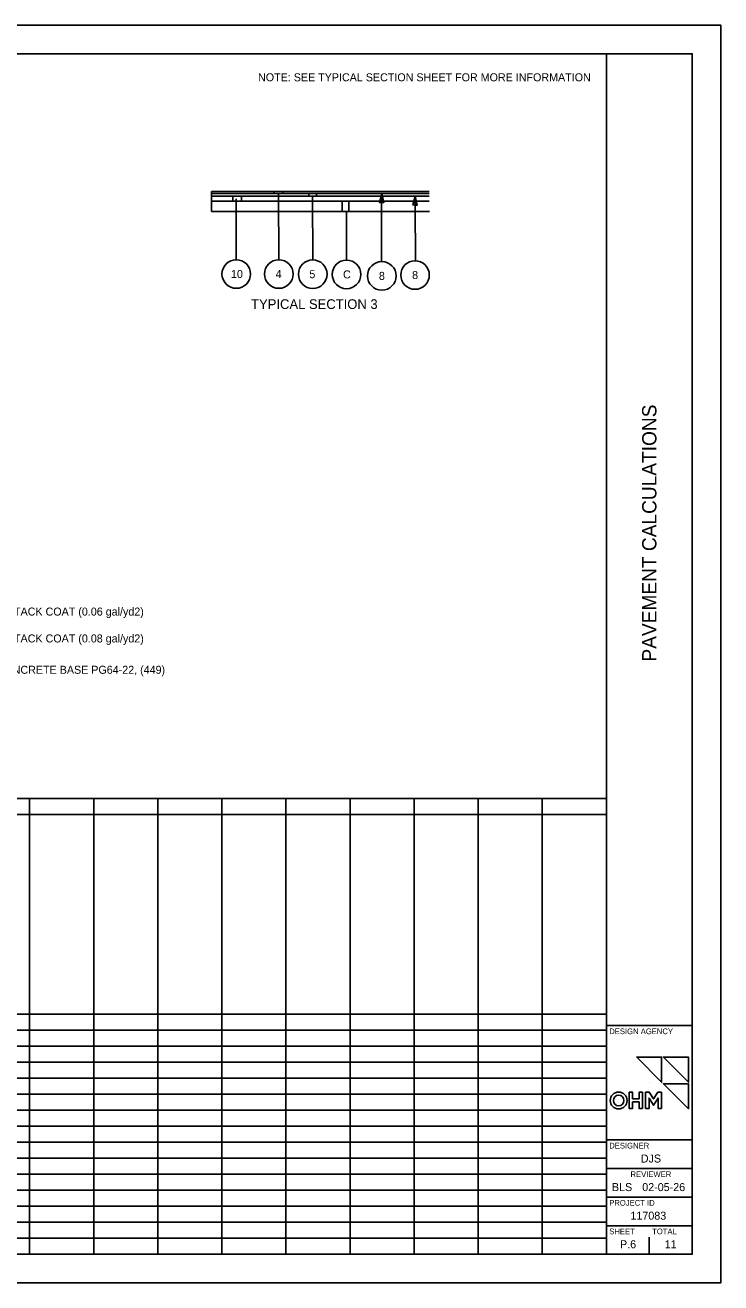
# Model space of a CAD drawing. Extents: x 0 to 34, y 0 to 22.
# Drawn here: x 21.84 to 34, y 0 to 22 of the extents above; entities that cross this region are included whole.
import ezdxf

# ---------------------------------------------------------------- set-up
doc = ezdxf.new("R2010")
doc.units = 0
for name, color, linetype in [('Default', 7, 'Continuous'), ('PV_P_EOP', 7, 'Continuous'), ('SC_Shading2', 7, 'Continuous'), ('SH_Border', 7, 'Continuous'), ('SH_Cut_Line', 7, 'Continuous'), ('SH_Data', 7, 'Continuous'), ('SH_Text', 7, 'Continuous'), ('TX_P_Misc', 7, 'Continuous')]:
    doc.layers.add(name, color=color, linetype=linetype)

msp = doc.modelspace()

# ---------------------------------------------------------------- linework, layer by layer
at = {"layer": 'Default'}
for p, q in [((25.101, 19.055), (28.904, 19.055)), ((25.101, 19.01), (28.905, 19.01)), ((25.101, 18.921), (28.905, 18.921)), ((25.101, 18.742), (28.91, 18.742)), ((1.5, 8.472), (32, 8.472)), ((21.921, 8.472), (21.921, 0.502)), ((23.041, 8.472), (23.041, 0.502)), ((24.161, 8.472), (24.161, 0.502)), ((25.281, 8.472), (25.281, 0.502)), ((26.401, 8.472), (26.401, 0.502)), ((27.521, 8.472), (27.521, 0.502)), ((28.64, 8.472), (28.64, 0.502)), ((29.76, 8.472), (29.76, 0.502)), ((30.88, 8.472), (30.88, 0.502)), ((32, 8.472), (32, 0.502)), ((11.842, 8.192), (32, 8.192)), ((7.363, 4.701), (32, 4.701)), ((1.5, 4.421), (32, 4.421)), ((1.5, 4.141), (32, 4.141)), ((1.5, 3.861), (32, 3.861)), ((1.5, 3.581), (32, 3.581)), ((1.5, 3.301), (32, 3.301)), ((1.5, 3.021), (32, 3.021)), ((1.5, 2.741), (32, 2.741)), ((1.5, 2.461), (32, 2.461)), ((1.5, 2.181), (32, 2.181)), ((1.5, 1.901), (32, 1.901)), ((1.5, 1.621), (32, 1.621)), ((1.5, 1.341), (32, 1.341)), ((1.5, 1.061), (32, 1.061)), ((1.5, 0.782), (32, 0.782)), ((1.5, 0.502), (32, 0.502))]:
    msp.add_line(p, q, dxfattribs=at)
for points in [[(32.966, 3.948), (32.966, 3.51), (32.53, 3.948)], [(33.433, 3.948), (33.433, 3.51), (32.997, 3.948)], [(32.397, 3.333), (32.457, 3.333), (32.457, 3.22), (32.571, 3.22), (32.571, 3.333), (32.631, 3.333), (32.631, 3.052), (32.571, 3.052), (32.571, 3.166), (32.457, 3.166), (32.457, 3.052), (32.397, 3.052)], [(32.9, 3.335), (32.963, 3.335), (32.963, 3.052), (32.903, 3.052), (32.903, 3.233), (32.824, 3.108), (32.745, 3.233), (32.745, 3.052), (32.685, 3.052), (32.685, 3.335), (32.748, 3.335), (32.824, 3.216)], [(33.433, 3.483), (33.433, 3.045), (32.997, 3.483)]]:
    msp.add_lwpolyline(points, close=True, dxfattribs=at)
at = {"layer": 'PV_P_EOP'}
for q in [(28.903, 19.088), (25.101, 18.742)]:
    msp.add_line((25.101, 19.088), q, dxfattribs=at)
at = {"layer": 'SC_Shading2'}
msp.add_lwpolyline([(27.501, 18.921), (27.383, 18.921), (27.383, 18.742), (27.501, 18.742)], close=True, dxfattribs=at)
at = {"layer": 'SH_Border'}
for p, q in [((32, 0.5), (32, 21.5)), ((32, 4.5), (33.5, 4.5)), ((32, 2.5), (33.5, 2.5)), ((32, 2), (33.5, 2)), ((32, 1.5), (33.5, 1.5)), ((32, 1), (33.5, 1))]:
    msp.add_line(p, q, dxfattribs=at)
msp.add_lwpolyline([(1.5, 21.5), (33.5, 21.5), (33.5, 0.5), (1.5, 0.5)], close=True, dxfattribs=at)
at = {"layer": 'SH_Cut_Line'}
msp.add_lwpolyline([(0, 0), (34, 0), (34, 22), (0, 22)], close=True, dxfattribs=at)
at = {"layer": 'SH_Data'}
for p, q in [((32.75, 3.5), (32.75, 3.5)), ((32.375, 0.675), (32.375, 0.675)), ((32.75, 0.5), (32.75, 0.8))]:
    msp.add_line(p, q, dxfattribs=at)
at = {"layer": 'SH_Text'}
for p, q in [((25.533, 17.897), (25.529, 18.962)), ((26.276, 17.897), (26.271, 19.055)), ((26.868, 17.894), (26.863, 19.01)), ((27.459, 17.89), (27.456, 18.742)), ((28.07, 17.864), (28.073, 18.899)), ((28.663, 17.879), (28.657, 18.854))]:
    msp.add_line(p, q, dxfattribs=at)
for points in [[(25.623, 19.008), (25.624, 18.921), (25.472, 18.921), (25.472, 19.008)], [(26.346, 19.088), (26.347, 19.055), (26.195, 19.055), (26.194, 19.088)], [(26.934, 19.055), (26.935, 19.01), (26.798, 19.01), (26.798, 19.055)], [(28.073, 18.899), (28.075, 19.055), (28.034, 18.9)], [(28.073, 18.899), (28.075, 19.055), (28.112, 18.899)], [(28.657, 18.854), (28.659, 19.01), (28.618, 18.855)], [(28.657, 18.854), (28.659, 19.01), (28.696, 18.854)]]:
    msp.add_lwpolyline(points, close=True, dxfattribs=at)
for centre in [(25.533, 17.647), (26.276, 17.647), (26.868, 17.644), (27.459, 17.64), (28.076, 17.614), (28.656, 17.629)]:
    msp.add_circle(centre, 0.25, dxfattribs=at)
at = {"layer": 'TX_P_Misc'}
for p, q in [((32.745, 3.052), (32.745, 3.233)), ((32.745, 3.233), (32.824, 3.108)), ((32.824, 3.108), (32.903, 3.233)), ((32.903, 3.233), (32.903, 3.052))]:
    msp.add_line(p, q, dxfattribs=at)
for points in [[(32.53, 3.948), (32.966, 3.51), (32.966, 3.948), (32.53, 3.948)], [(32.997, 3.948), (33.433, 3.51), (33.433, 3.948), (32.997, 3.948)], [(32.824, 3.216), (32.748, 3.335), (32.685, 3.335), (32.685, 3.052), (32.745, 3.052)], [(32.903, 3.052), (32.963, 3.052), (32.963, 3.335), (32.9, 3.335), (32.824, 3.216)], [(32.997, 3.483), (33.433, 3.045), (33.433, 3.483), (32.997, 3.483)]]:
    msp.add_lwpolyline(points, dxfattribs=at)
msp.add_lwpolyline([(32.397, 3.333), (32.457, 3.333), (32.457, 3.22), (32.571, 3.22), (32.571, 3.333), (32.631, 3.333), (32.631, 3.052), (32.571, 3.052), (32.571, 3.166), (32.457, 3.166), (32.457, 3.052), (32.397, 3.052)], close=True, dxfattribs=at)
for radius in [0.148, 0.148, 0.0927, 0.0927]:
    msp.add_circle((32.215, 3.19), radius, dxfattribs=at)

# ---------------------------------------------------------------- texts
at = {"layer": 'Default'}
for s, p in [('NOTE: SEE TYPICAL SECTION SHEET FOR MORE INFORMATION', (25.913, 21.018)), ('ITEM 407 - NON-TRACKING TACK COAT (0.06 gal/yd2)', (19.173, 11.672)), ('ITEM 407 - NON-TRACKING TACK COAT (0.08 gal/yd2)', (19.173, 11.202)), ('4" ASPHALT CONCRETE BASE PG64-22, (449)', (20.217, 10.654))]:
    msp.add_text(s, height=0.14, dxfattribs=at).set_placement(p)
at = {"layer": 'SH_Data'}
msp.add_text('PAVEMENT CALCULATIONS', height=0.25, rotation=90, dxfattribs=at).set_placement((32.875, 10.868))
for s, height, p in [('DESIGN AGENCY', 0.1, (32.05, 4.35)), ('DESIGNER', 0.1, (32.05, 2.35)), ('DJS', 0.14, (32.602, 2.105)), ('REVIEWER', 0.1, (32.422, 1.85)), ('BLS', 0.14, (32.097, 1.605)), ('02-05-26', 0.14, (32.627, 1.605)), ('PROJECT ID', 0.1, (32.05, 1.35)), ('117083', 0.14, (32.421, 1.105)), ('SHEET', 0.1, (32.05, 0.85)), ('TOTAL', 0.1, (32.8, 0.85)), ('P.6', 0.14, (32.239, 0.605)), ('11', 0.14, (33.019, 0.605))]:
    msp.add_text(s, height=height, dxfattribs=at).set_placement(p)
at = {"layer": 'SH_Text'}
for s, height, p in [('10', 0.14, (25.44, 17.577)), ('4', 0.14, (26.22, 17.577)), ('5', 0.14, (26.81, 17.574)), ('C', 0.14, (27.398, 17.57)), ('8', 0.14, (28.025, 17.544)), ('8', 0.14, (28.605, 17.559)), ('TYPICAL SECTION 3', 0.17, (25.792, 17.035))]:
    msp.add_text(s, height=height, dxfattribs=at).set_placement(p)

doc.saveas('drawing.dxf')
